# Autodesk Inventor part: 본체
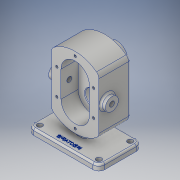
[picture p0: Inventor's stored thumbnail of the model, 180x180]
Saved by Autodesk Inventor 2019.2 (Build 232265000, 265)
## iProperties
Created: 2019-03
Part Number: 본체
Material: 알루미늄 6061
Document SubType Name: Modeling
Designer: User
Density: 2.7 g/cm^3
Appearance: 알루미늄 - 평지
Mass: 1186.46 g
Surface Area: 720.472 cm^2
Volume: 439.43 cm^3
Author: User
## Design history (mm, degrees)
sketch "스케치1"
  geometry: L1 (-40, 122.721)-(-40, 33.279); L2 (40, 122.721)-(40, 33.279); L3 (0, 165.6)-(0, -27.6) reference; L4 (-56, 0)-(56, 0) reference; A1 r 60 centre (0, 78) between (-40, 33.279) and (40, 33.279); A2 r 60 centre (0, 78) between (40, 122.721) and (-40, 122.721); 1 further point
  constraints: 4 end point, 4 point on circle, 2 centre point, 2 vertical, 1 point on line
  dimensions: "d2" = 80 distance between parallel lines of L2 L1; "d3" = 40 distance between parallel lines of L2 L3; "d6" = 60 radius of A2; "d7" = 60 radius of A1; "d8" = 78 distance from line of L4 A1.centre
extrude "돌출1" new body sketch "스케치1" distance "d9" = 53; taper "d10" = 0 deg
sketch "스케치2"
  geometry: L1 (-60, 73)-(60, 73); L2 (60, 73)-(60, 0); L3 (60, 0)-(-60, 0); L4 (-60, 0)-(-60, 73); L5 (0, -14.6)-(0, 87.6) reference; L6 (-84, 0)-(84, 0) reference; 1 further point
  constraints: 8 end point, 2 parallel, 1 horizontal, 1 perpendicular
  dimensions: "d11" = 73 distance between parallel lines of L3 L1; "d12" = 120 distance between parallel lines of L4 L2; "d13" = 60 distance between parallel lines of L2 L5; "d14" = 0 distance between parallel lines of L6 L3
extrude "돌출2" join sketch "스케치2" distance "d15" = 10; taper "d16" = 0 deg
sketch "스케치3"
  geometry: L1 (6, -43)-(-6, -43); L2 (-6, -43)-(-6, 0); L3 (-6, 0)-(6, 0); L4 (6, 0)-(6, -43); L5 (84, 0)-(-84, 0) reference; L6 (0, 14.6)-(0, -87.6) reference; 1 further point
  constraints: 8 end point, 2 parallel, 1 horizontal, 1 perpendicular
  dimensions: "d17" = 12 distance of L1.start L1.end; "d18" = 43 distance of L3.end L1.start; "d19" = 0 distance between parallel lines of L5 L3; "d20" = 6 distance between parallel lines of L6 L2
extrude "돌출3" join sketch "스케치3" distance "d21" = 12; taper "d22" = 0 deg
sketch "스케치4"
  geometry: L1 (-53, 0)-(-53, 89.443) reference; L2 (-87.6, -33.279)-(14.6, -33.279) reference; C1 r 11 at (-39, 44.721); 1 further point
  constraints: 1 centre point
  dimensions: "d23" = 22 diameter of C1; "d24" = 14 distance from line of L1 C1.centre; "d25" = 78 distance from line of L2 C1.centre
extrude "돌출4" join sketch "스케치4" distance "d26" = 8; taper "d27" = 0 deg
sketch "스케치5"
  geometry: L1 (60, 0)-(-60, 0) reference; L2 (0, -27.6)-(0, 165.6) reference; C1 r 19 at (0, 100); 1 further point
  constraints: 1 centre point, 1 point on line
  dimensions: "d28" = 38 diameter of C1; "d29" = 100 distance from line of L1 C1.centre
extrude "돌출5" join sketch "스케치5" distance "d30" = 17; taper "d31" = 0 deg
sketch "스케치6"
  geometry: L1 (0, 32)-(0, 124); L2 (-24, 56)-(-24, 100); L3 (24, 100)-(24, 56); L4 (0, 165.6)-(0, -27.6) reference; L5 (-84, 0)-(84, 0) reference; A1 r 24 centre (0, 56) between (-24, 56) and (24, 56); A2 r 24 centre (0, 100) between (24, 100) and (-24, 100); 2 further points
  constraints: 8 end point, 6 point on circle, 4 tangent, 3 point on line, 2 centre point, 1 midpoint, 1 parallel, 1 vertical
  dimensions: "d32" = 24 distance between parallel lines of L1 L3; "d33" = 44 distance of A1.centre A2.centre; "d34" = 78 distance from line of L5 point (0, 78)
extrude "돌출6" cut sketch "스케치6" distance "d35" = 29; taper "d36" = 0 deg
sketch "스케치7"
  geometry: C1 r 19 at (0, 0) reference; 2 further points
  constraints: 1 coincident
hole "구멍1" sketch "스케치7" at (0, 0) diameter "d37" = 17; stored, may be unused: countersink angle "d41" = 82 deg, drill point angle "d43" = 0 deg; dims "d38" = 8, "d39" = 28, "d40" = 7.3, "d42" = 50
sketch "스케치8"
  geometry: C1 r 8.5 at (0, 100) reference; 2 further points
  constraints: 1 coincident
hole "구멍2" sketch "스케치8" at (0, 100) diameter "d44" = 25; stored, may be unused: countersink angle "d48" = 82 deg, drill point angle "d50" = 0 deg; dims "d45" = 8, "d46" = 28, "d47" = 7.3, "d49" = 15
sketch "스케치9"
  geometry: A1 r 24 centre (0, 56) between (-24, 56) and (24, 56) reference; 2 further points
  constraints: 1 coincident
hole "구멍3" sketch "스케치9" at (0, 56) diameter "d51" = 25; stored, may be unused: countersink angle "d55" = 82 deg, drill point angle "d57" = 0 deg; dims "d52" = 8, "d53" = 28, "d54" = 7.3, "d56" = 15
sketch "스케치10"
  geometry: C1 r 11 at (0, 0) reference; 2 further points
  constraints: 1 coincident
hole "구멍4" sketch "스케치10" at (0, 0) diameter "d58" = 8.376; stored, may be unused: countersink angle "d62" = 82 deg, drill point angle "d64" = 0 deg; dims "d59" = 40, "d60" = 28, "d61" = 7.3, "d63" = 40
sketch "스케치11"
  geometry: C1 r 11 at (0, 0) reference; 2 further points
  constraints: 1 coincident
hole "구멍5" sketch "스케치11" at (0, 0) diameter "d65" = 8.376; stored, may be unused: countersink angle "d69" = 82 deg, drill point angle "d71" = 0 deg; dims "d66" = 40, "d67" = 28, "d68" = 7.3, "d70" = 40
sketch "스케치12"
  geometry: L1 (0, 56)-(0, 100); L2 (31, 56)-(31, 100); L3 (-31, 100)-(-31, 56); L4 (0, 165.6)-(0, -27.6) reference; C1 r 8.5 at (0, 100) reference; A1 r 31 centre (0, 56) between (-31, 56) and (31, 56); A2 r 31 centre (0, 100) between (31, 100) and (-31, 100); 8 further points
  constraints: 9 point on circle, 8 end point, 4 tangent, 3 point on line, 2 centre point, 1 midpoint, 1 parallel, 1 vertical
  dimensions: "d79" = 31 radius of A2; "d80" = 44 distance of L1.start L1.end; "d81" = 44 distance of point (31, 56) point (31, 100); "d82" = 44 distance of point (-31, 56) point (-31, 100); "d83" = 22 vertical distance of point (0, 78) point (-31, 100); "d84" = 22 vertical distance of point (0, 78) point (31, 100)
hole "구멍6" sketch "스케치12" at (31, 100), (0, 131), (-31, 100), (-31, 56), (31, 56), (0, 25) diameter "d72" = 4.134; stored, may be unused: countersink angle "d76" = 82 deg, drill point angle "d78" = 118 deg; dims "d73" = 10, "d74" = 28, "d75" = 7.3, "d77" = 12
fillet "모깎기1" dims "d85" = 10
fillet "모깎기3" dims "d94" = 3
fillet "모깎기4" dims "d95" = 10
fillet "모깎기7" dims "d98" = 3
fillet "모깎기10" dims "d101" = 3
fillet "모깎기11" dims "d102" = 3
fillet "모깎기12" dims "d103" = 3
sketch "스케치14"
  geometry: A1 r 7 centre (50, -63) between (50, -70) and (57, -63) reference; A2 r 7 centre (-50, -63) between (-57, -63) and (-50, -70) reference; A3 r 7 centre (50, -10) between (57, -10) and (50, -3) reference; A4 r 7 centre (-50, -10) between (-50, -3) and (-57, -10) reference; 5 further points
  constraints: 4 coincident
hole "구멍8" sketch "스케치14" at (50, -63), (-50, -63), (50, -10), (-50, -10) diameter "d104" = 9; stored, may be unused: countersink angle "d108" = 82 deg, drill point angle "d110" = 0 deg; dims "d105" = 10, "d106" = 28, "d107" = 7.3, "d109" = 12
chamfer "모따기1" distance "d111" = 1; stored, may be unused: second distance "d112" = 2, angle "d113" = 45 deg
chamfer "모따기4" distance "d120" = 0.7; stored, may be unused: second distance "d121" = 2, angle "d122" = 30 deg
fillet "모깎기13" dims "d123" = 0.5
sketch "스케치17"
  geometry: L1 (-50, -73)-(50, -73) reference; L2 (-60, -10)-(-60, -63) reference; 2 further points
  constraints: 1 other
  dimensions: "d124" = 10 distance from line of L1 point (0, -63); "d125" = 60 distance from line of L2 point (0, -63)
feature "엠보싱1" sketch "스케치17" dims "d2" = 80, "d3" = 40, "d6" = 60, "d7" = 60, "d8" = 78, "d17" = 12, "d18" = 43, "d19" = 0, "d20" = 6, "d126" = 0.5, "d127" = 0
fillet "모깎기14" dims "d128" = 3
node "솔리드1"
mirror "미러1"
